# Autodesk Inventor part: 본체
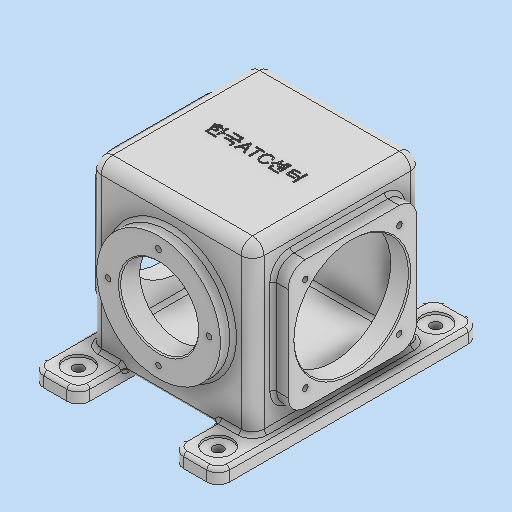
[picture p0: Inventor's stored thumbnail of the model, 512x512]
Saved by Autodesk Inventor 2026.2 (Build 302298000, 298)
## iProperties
Created: 2026-01
Part Number: 본체
Material: 일반
Document SubType Name: Modeling
Designer: PC2-07
Density: 1 g/cm^3
Appearance: 기본값
Mass: 901.565 g
Surface Area: 2483.61 cm^2
Volume: 901.565 cm^3
Author: PC2-07
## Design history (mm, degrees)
sketch "스케치1"
  geometry: L1 (-71, 74)-(71, 74); L2 (71, 74)-(71, -74); L3 (71, -74)-(-71, -74); L4 (-71, -74)-(-71, 74); L5 (-71, 74)-(71, -74); L6 (71, 74)-(-71, -74); L7 (0, 105.69)-(0, -105.69); L8 (-81, -70)-(-41, -70); L9 (-41, -70)-(-41, -82); L10 (-41, -82)-(-81, -82); L11 (-81, -82)-(-81, -70); L12 (81, -70)-(41, -70); L13 (41, -70)-(41, -82); L14 (41, -82)-(81, -82); L15 (81, -82)-(81, -70); 3 further points
  constraints: 30 end point, 5 symmetric about line, 4 parallel, 3 midpoint, 2 horizontal, 2 perpendicular, 1 point on line, 1 vertical
  dimensions: "d0" = 142 distance of L2.end L3.end; "d1" = 148 distance of L1.end L2.end; "d54" = 8 distance between parallel lines of L3 L10; "d55" = 12 distance of L10.end L8.start; "d56" = 40 distance of L9.end L10.end; "d57" = 162 distance between parallel lines of L11 L15
extrude "돌출1" new body sketch "스케치1" stored distance "d6" = 148; taper "d7" = 0 deg
sketch "스케치2"
  geometry: C1 r 54 at (0, 0); 1 further point
  constraints: 1 centre point, 1 coincident
  dimensions: "d10" = 108 diameter of C1
extrude "돌출3" join sketch "스케치2" distance "d11" = 11; taper "d12" = 0 deg
node "작업 평면1"
sketch "스케치3"
  geometry: L1 (141.5, -6.5)-(6.5, -6.5); L2 (6.5, -6.5)-(6.5, -141.5); L3 (6.5, -141.5)-(141.5, -141.5); L4 (141.5, -141.5)-(141.5, -6.5); L5 (141.5, -6.5)-(6.5, -141.5); L6 (6.5, -6.5)-(141.5, -141.5); 1 further point
  constraints: 12 end point, 2 midpoint, 2 parallel, 1 horizontal, 1 perpendicular
  dimensions: "d14" = 135 distance of L3.end L2.end; "d15" = 135 distance of L2.end L1.end
extrude "돌출4" cut sketch "스케치3" stored distance "d16" = 135; taper "d17" = 0 deg
sketch "스케치4"
  geometry: C1 r 34 at (0, 0); 1 further point
  constraints: 1 centre point, 1 coincident
  dimensions: "d18" = 68 diameter of C1
extrude "돌출5" cut sketch "스케치4" distance "d19" = 86; taper "d20" = 0 deg
sketch "스케치5"
  geometry: A1 r 44 centre (0, 0) between (0, 44) and (44, 0); 3 further points
  constraints: 4 point on circle, 1 centre point, 1 coincident
  dimensions: "d21" = 88 diameter of A1
hole "구멍1" sketch "스케치5" at (0, -44), (-44, 0), (0, 44), (44, 0) diameter "d22" = 4.917; stored, may be unused: countersink angle "d26" = 90 deg, drill point angle "d28" = 118 deg; dims "d23" = 12, "d24" = 10, "d25" = 2, "d27" = 14
sketch "스케치6"
  geometry: L1 (18, -18)-(130, -18); L2 (130, -18)-(130, -130); L3 (130, -130)-(18, -130); L4 (18, -130)-(18, -18); L5 (18, -18)-(130, -130); L6 (130, -18)-(18, -130); 1 further point
  constraints: 12 end point, 2 midpoint, 2 parallel, 1 horizontal, 1 perpendicular
  dimensions: "d29" = 112 distance of L2.end L3.end; "d30" = 112 distance of L1.end L2.end
extrude "돌출6" join sketch "스케치6" distance "d31" = 13; taper "d32" = 0 deg
sketch "스케치7"
  geometry: C1 r 50 at (74, -74); 1 further point
  constraints: 1 centre point, 1 coincident
  dimensions: "d33" = 100 diameter of C1
extrude "돌출7" cut sketch "스케치7" distance "d34" = 79.25; taper "d35" = 0 deg
fillet "모깎기1" dims "d36" = 15
fillet "모깎기2" dims "d37" = 3
sketch "스케치8"
  geometry: L1 (33, -33)-(115, -33); L2 (115, -33)-(115, -115); L3 (115, -115)-(33, -115); L4 (33, -115)-(33, -33); L5 (33, -33)-(115, -115); L6 (115, -33)-(33, -115); 5 further points
  constraints: 12 end point, 4 coincident, 2 midpoint, 2 parallel, 1 horizontal, 1 perpendicular
  dimensions: "d38" = 82 distance of L2.end L3.end; "d39" = 82 distance of L1.end L2.end
hole "구멍2" sketch "스케치8" at (33, -33), (115, -33), (115, -115), (33, -115) diameter "d40" = 4.917; stored, may be unused: countersink angle "d44" = 90 deg, drill point angle "d46" = 118 deg; dims "d41" = 12, "d42" = 4, "d43" = 2, "d45" = 14
fillet "모깎기3" dims "d47" = 3
fillet "모깎기4" dims "d48" = 10
fillet "모깎기5" dims "d49" = 10
extrude "돌출8" join sketch "스케치1" stored distance "d58" = 228; taper "d59" = 0 deg
fillet "모깎기8" dims "d60" = 10
fillet "모깎기9" dims "d61" = 3
sketch "스케치9"
  geometry: L1 (10, -30)-(132, -30); L2 (11.823, 158)-(133.823, 158); L3 (142, 178)-(122, 178) reference; 5 further points
  constraints: 4 coincident, 4 end point, 2 horizontal
  dimensions: "d69" = 188 distance from line of L2 point (132, -30); "d70" = 122 distance of L2.start L2.end; "d71" = 122 distance of L1.start L1.end; "d72" = 20 distance between parallel lines of L3 L2
hole "구멍3" sketch "스케치9" at (10, -30), (132, -30), (133.823, 158), (11.823, 158) diameter "d62" = 9; stored, may be unused: countersink angle "d66" = 90 deg, drill point angle "d68" = 0 deg; dims "d63" = 12, "d64" = 24, "d65" = 2, "d67" = 14
fillet "모깎기10" dims "d73" = 3
fillet "모깎기11" dims "d74" = 3
fillet "모깎기12" dims "d75" = 3
sketch "스케치11"
  geometry: 2 further points
  constraints: 1 coincident, 1 other
feature "엠보싱1" sketch "스케치11" dims "d0" = 142, "d1" = 148, "d14" = 135, "d15" = 135, "d54" = 8, "d55" = 12, "d56" = 40, "d57" = 162, "d76" = 0.5, "d77" = 0
chamfer "모따기1" distance "d78" = 1; stored, may be unused: second distance "d79" = 2, angle "d80" = 45 deg
chamfer "모따기2" distance "d81" = 1; stored, may be unused: second distance "d82" = 2, angle "d83" = 45 deg
feature "ͭ耀ͯ耀ͱ耀ͳ耀͵耀ͷ耀͹耀ͻ耀" dims "d0" = 142, "d1" = 148, "d6" = 148, "d7" = 0, "d10" = 108, "d11" = 11, "d12" = 0, "d13" = -71, "d14" = 135, "d15" = 135, "d16" = 135, "d17" = 0, "d18" = 68, "d19" = 86, "d20" = 0, "d21" = 88, "d22" = 4.917, "d23" = 12, "d24" = 10, "d25" = 2, "d26" = 90 deg, "d27" = 14, "d28" = 118 deg, "d29" = 112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
node "솔리드1"
mirror "미러1"
feature "A9D066F2-1C7D-4E18-AEED-F7BC21143FA4" dims "d62" = 9, "d63" = 12, "d64" = 24, "d65" = 2, "d66" = 90 deg, "d67" = 14, "d68" = 0
